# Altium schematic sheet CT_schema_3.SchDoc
size 276 x 169 mm
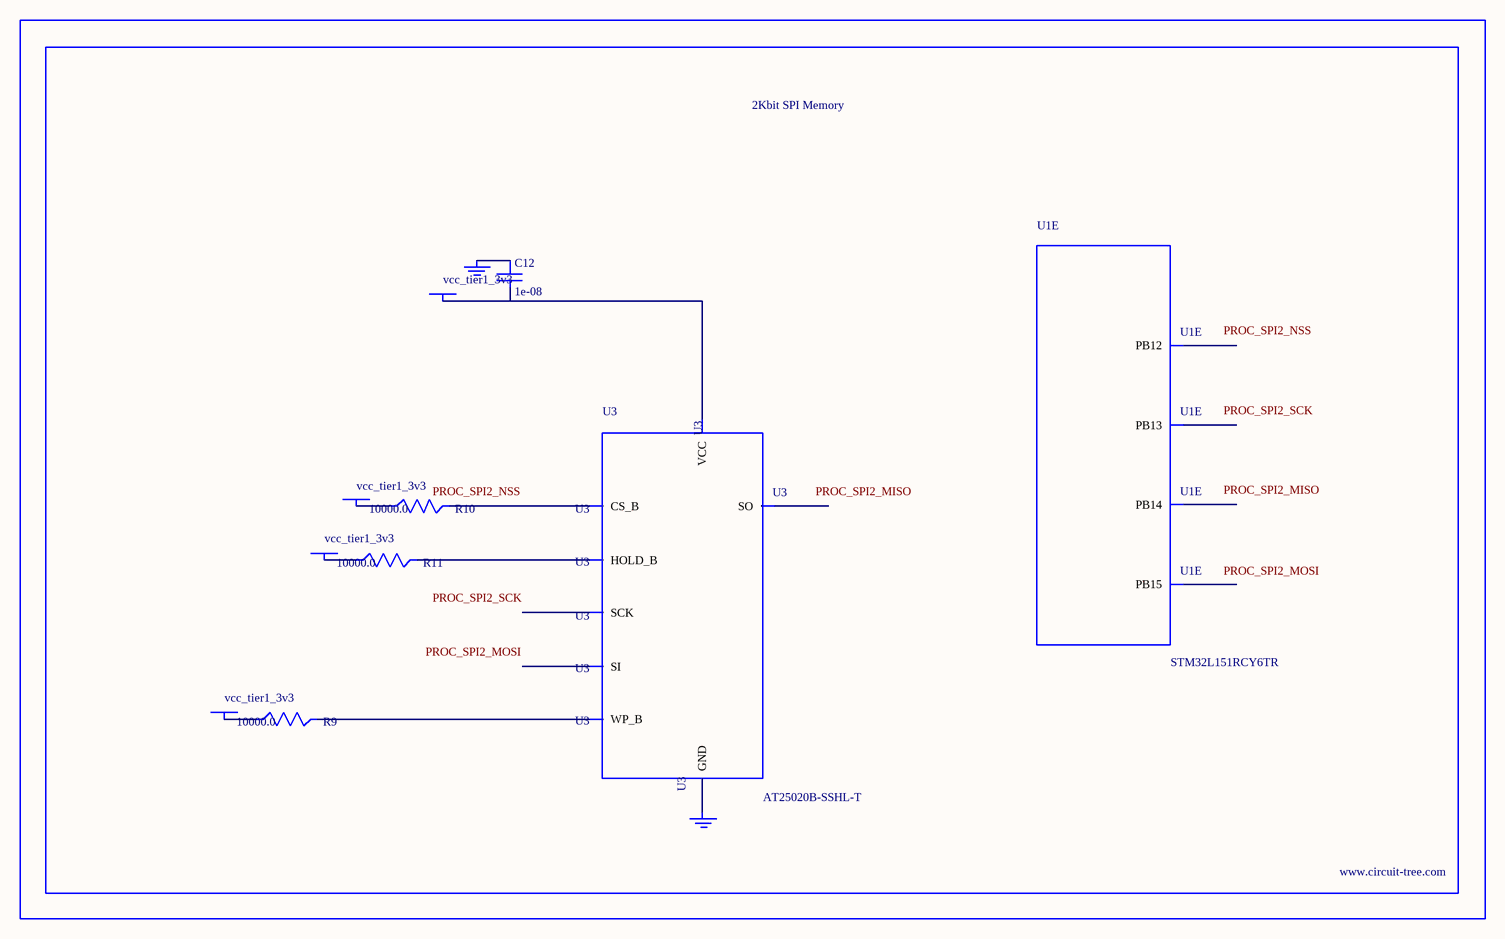
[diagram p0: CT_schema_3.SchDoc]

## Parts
BORDER2  (no value)
C12  1e-08  [C0402]
GND_INSTANCE_2_0  (no value)
GND_INSTANCE_2_1  (no value)
POWER_INSTANCE_2_0  vcc_tier1_3v3
POWER_INSTANCE_2_1  vcc_tier1_3v3
POWER_INSTANCE_2_2  vcc_tier1_3v3
POWER_INSTANCE_2_3  vcc_tier1_3v3
R9  10000.0  [R0603]
R10  10000.0  [R0603]
R11  10000.0  [R0603]
U1  STM32L151RCY6TR  [WLCSP64]  (part E of 6)
U3  AT25020B-SSHL-T  [SOIC-8]

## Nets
NetC12_1: C12.1 GND_INSTANCE_2_0.0(GND)
NetC12_2: C12.2 POWER_INSTANCE_2_3.0(PWR) U3.8(VCC)
NetGND_INSTANCE_2_1_0: GND_INSTANCE_2_1.0(GND) U3.4(GND)
NetPOWER_INSTANCE_2_0_0: POWER_INSTANCE_2_0.0(PWR) R10.1
NetPOWER_INSTANCE_2_1_0: POWER_INSTANCE_2_1.0(PWR) R9.1
NetPOWER_INSTANCE_2_2_0: POWER_INSTANCE_2_2.0(PWR) R11.1
NetR9_2: R9.2 U3.3(WP_B)
NetR10_2: R10.2 U3.1(CS_B)
NetR11_2: R11.2 U3.7(HOLD_B)

Not connected (* = marked no-connect by the designer): U1 F1(PB15) F2(PB14) G1(PB13) G2(PB12); U3 2(SO) 5(SI) 6(SCK)

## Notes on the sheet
- Labels drawn without touching a wire or pin: PROC_SPI2_MISO, PROC_SPI2_MOSI, PROC_SPI2_NSS, PROC_SPI2_SCK

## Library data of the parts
BORDER2 = BORDER_PAGE2
C12 = C0402C103K3RAC
GND_INSTANCE_2_0 GND_INSTANCE_2_1 = GND
POWER_INSTANCE_2_0-POWER_INSTANCE_2_3 = PWR
R9-R11 = RC0603JR-0710KL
